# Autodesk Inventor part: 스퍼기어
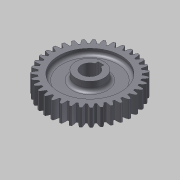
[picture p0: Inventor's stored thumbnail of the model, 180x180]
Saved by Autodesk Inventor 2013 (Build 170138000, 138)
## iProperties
Created: 2013-08
Part Number: 스퍼기어
Material: 강
Document SubType Name: Modeling
Designer: 한국산업디자인학원
Categories: <?xml version="1.0" encoding="UTF-16"?> <MemberInstance><Categories><FamilyTemplate><FamilyTemplateParameter ValueType="xs:double" Id="1" ObjectReferenceKey="da
Density: 1 g/cm^3
CustomPartVersion: 1
Author: 한국산업디자인학원
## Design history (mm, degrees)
sketch "Sketch1"
  geometry: C1 r 37 at (0, 0)
  constraints: 1 centre point
  dimensions: "d0" = 74 diameter of C1 (= da_da)
extrude "Extrusion1" new body sketch "Sketch1" distance "d1" = 15 (= da_b); taper "d2" = 0 deg
workplane "Work Plane2"
feature "피치 지름" dims "d4" = 10, "d5" = 0
workplane "Work Plane8"
workplane "Work Plane9"
feature "스퍼 기어" dims "da_b" = 15, "da_d" = 70, "da_aw" = 70, "da_da" = 74, "da_df" = 65, "da_dw" = 70, angle "da_beta" = 0 deg, "da_lefttooth" = 0, "da_righttooth" = 0
sketch "스케치3"
  geometry: L1 (-0.05, 18)-(12.45, 18); L2 (12.45, 18)-(12.45, -13); L3 (12.45, -13)-(-0.05, -13); L4 (31.515, 0)-(36.248, 0) reference; L5 (36.248, 0)-(36.544, 0) reference; L6 (36.544, 0)-(32.296, 0) reference; L7 (32.296, 0)-(32.426, 0) reference; L8 (32.426, 0)-(36.991, 0) reference; L9 (36.991, 0)-(36.991, 0) reference; L10 (36.991, 0)-(32.426, 0) reference; L11 (32.426, 0)-(32.296, 0) reference; L12 (32.296, 0)-(36.544, 0) reference; L13 (36.544, 0)-(36.248, 0) reference; L14 (36.248, 0)-(31.515, 0) reference; L15 (31.515, 0)-(31.127, 0) reference; L16 (31.127, 0)-(34.924, 0) reference; L17 (34.924, 0)-(34.34, 0) reference; L18 (34.34, 0)-(29.591, 0) reference; L19 (29.591, 0)-(28.958, 0) reference; L20 (28.958, 0)-(32.18, 0) reference; L21 (32.18, 0)-(31.329, 0) reference; L22 (31.329, 0)-(26.715, 0) reference; L23 (26.715, 0)-(25.858, 0) reference; L24 (25.858, 0)-(28.403, 0) reference; L25 (28.403, 0)-(27.31, 0) reference; L26 (27.31, 0)-(22.981, 0) reference; L27 (22.981, 0)-(21.927, 0) reference; L28 (21.927, 0)-(23.712, 0) reference; L29 (23.712, 0)-(22.414, 0) reference; L30 (22.414, 0)-(18.508, 0) reference; L31 (18.508, 0)-(17.291, 0) reference; L32 (17.291, 0)-(18.26, 0) reference; L33 (18.26, 0)-(16.798, 0) reference; L34 (16.798, 0)-(13.441, 0) reference; L35 (13.441, 0)-(12.1, 0) reference; L36 (12.1, 0)-(12.22, 0) reference; L37 (12.22, 0)-(10.641, 0) reference; L38 (10.641, 0)-(7.941, 0) reference; L39 (7.941, 0)-(6.519, 0) reference; L40 (6.519, 0)-(5.788, 0) reference; L41 (5.788, 0)-(4.143, 0) reference; L42 (4.143, 0)-(2.186, 0) reference; L43 (2.186, 0)-(0.729, 0) reference; L44 (0.729, 0)-(-0.83, 0) reference; L45 (-0.83, 0)-(-2.489, 0) reference; L46 (-2.489, 0)-(-3.639, 0) reference; L47 (-3.639, 0)-(-5.084, 0) reference; L48 (-5.084, 0)-(-7.422, 0) reference; L49 (-7.422, 0)-(-9.041, 0) reference; L50 (-9.041, 0)-(-9.347, 0) reference; L51 (-9.347, 0)-(-10.734, 0) reference; L52 (-10.734, 0)-(-13.775, 0) reference; L53 (-13.775, 0)-(-15.302, 0) reference; L54 (-15.302, 0)-(-14.755, 0) reference; L55 (-14.755, 0)-(-16.039, 0) reference; L56 (-16.039, 0)-(-19.685, 0) reference; L57 (-19.685, 0)-(-21.071, 0) reference; L58 (-21.071, 0)-(-19.688, 0) reference; L59 (-19.688, 0)-(-20.828, 0) reference; L60 (-20.828, 0)-(-24.963, 0) reference; L61 (-24.963, 0)-(-26.163, 0) reference; L62 (-26.163, 0)-(-23.989, 0) reference; L63 (-23.989, 0)-(-24.948, 0) reference; L64 (-24.948, 0)-(-29.438, 0) reference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; 2 further points
  constraints: 10 end point, 2 equal length, 2 perpendicular, 1 horizontal, 1 midpoint, 1 vertical alignment
  dimensions: "d52" = 31 distance between parallel lines of L1 L3; "d54" = 3 distance from line of L1 L170.end; "d55" = 25 diameter of L2 L284
revolve "회전1" sketch "스케치3" stored, may be unused: angle "d56" = 90 deg
sketch "스케치4"
  geometry: L1 (-12.55, 18)-(12.45, 18) reference; L2 (12.45, 0)-(-12.55, 0) reference; L3 (-12.55, -13)-(12.45, -13) reference; L4 (-0.05, 18)-(-0.05, -13); L5 (-0.05, 18)-(-7.55, 18); L6 (-7.55, -13)-(-0.05, -13); L7 (-7.55, -13)-(-7.55, 18); L8 (-0.05, 18)-(-0.05, -13); L9 (-27.55, 5)-(-12.55, 5); L10 (-12.55, 5)-(-12.55, 0); L11 (-12.55, 0)-(-27.55, 0); L12 (-27.55, 0)-(-27.55, 5); L13 (-27.55, 15)-(-12.55, 15); L14 (-12.55, 15)-(-12.55, 10); L15 (-12.55, 10)-(-27.55, 10); L16 (-27.55, 10)-(-27.55, 15); 5 further points
  constraints: 26 end point, 5 midpoint, 4 collinear, 4 parallel, 3 perpendicular, 2 horizontal, 2 horizontal alignment, 2 point on line
  dimensions: "d57" = 15 diameter of L7 L4; "d64" = 25 diameter of L10 L4; "d65" = 55 diameter of L12 L4; "d66" = 5 distance of L11.end L9.start; "d67" = 5 distance between parallel lines of L13 L15
revolve "회전2" sketch "스케치4" stored, may be unused: angle "d58" = 90 deg
sketch "스케치7"
  geometry: L1 (-2.5, 9.8)-(2.5, 9.8); L2 (2.5, 9.8)-(2.5, 0); L3 (2.5, 0)-(-2.5, 0); L4 (-2.5, 0)-(-2.5, 9.8); C1 r 7.5 at (0, 0) reference; 2 further points
  constraints: 8 end point, 2 parallel, 1 coincident, 1 horizontal, 1 midpoint, 1 perpendicular
  dimensions: "d68" = 9.8 distance from line of C1.centre L1; "d69" = 5 distance of L1.start L1.end
extrude "돌출3" cut sketch "스케치7" stored distance "d70" = 10; taper "d71" = 0 deg
fillet "모깎기1" dims "d72" = 3
body "Solid1"
sketch "Sketch2"
  geometry: C1 r 37 at (0, 0) reference; C2 r 35 at (0, 0)
  constraints: 1 centre point, 1 coincident
  dimensions: "d3" = 70 diameter of C2 (= da_dw)
body "Srf1"
node "투영된 루프1"
node "투영된 루프2"
other parameters: "d17" = 0, "d34" = 0.8976 (computed from da_z), "d39" = 0, "d41" = 0, "d47" = 0, "d48" = 0
